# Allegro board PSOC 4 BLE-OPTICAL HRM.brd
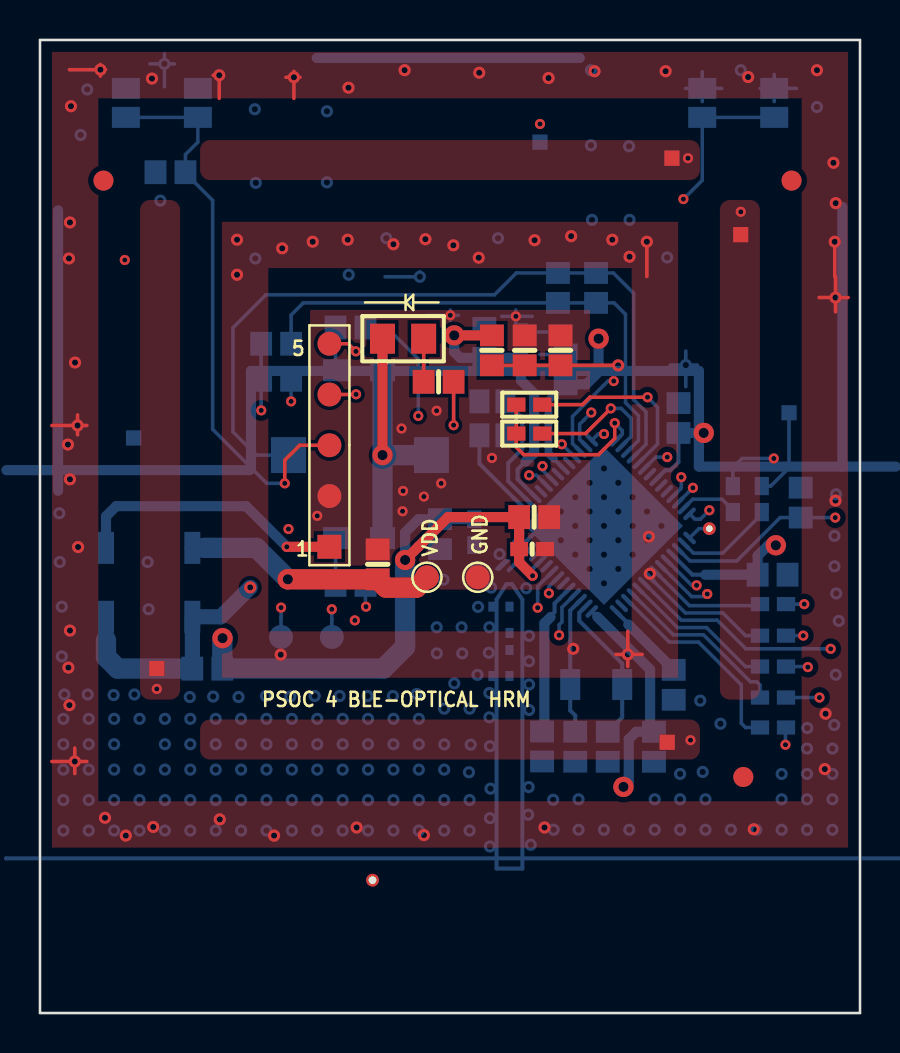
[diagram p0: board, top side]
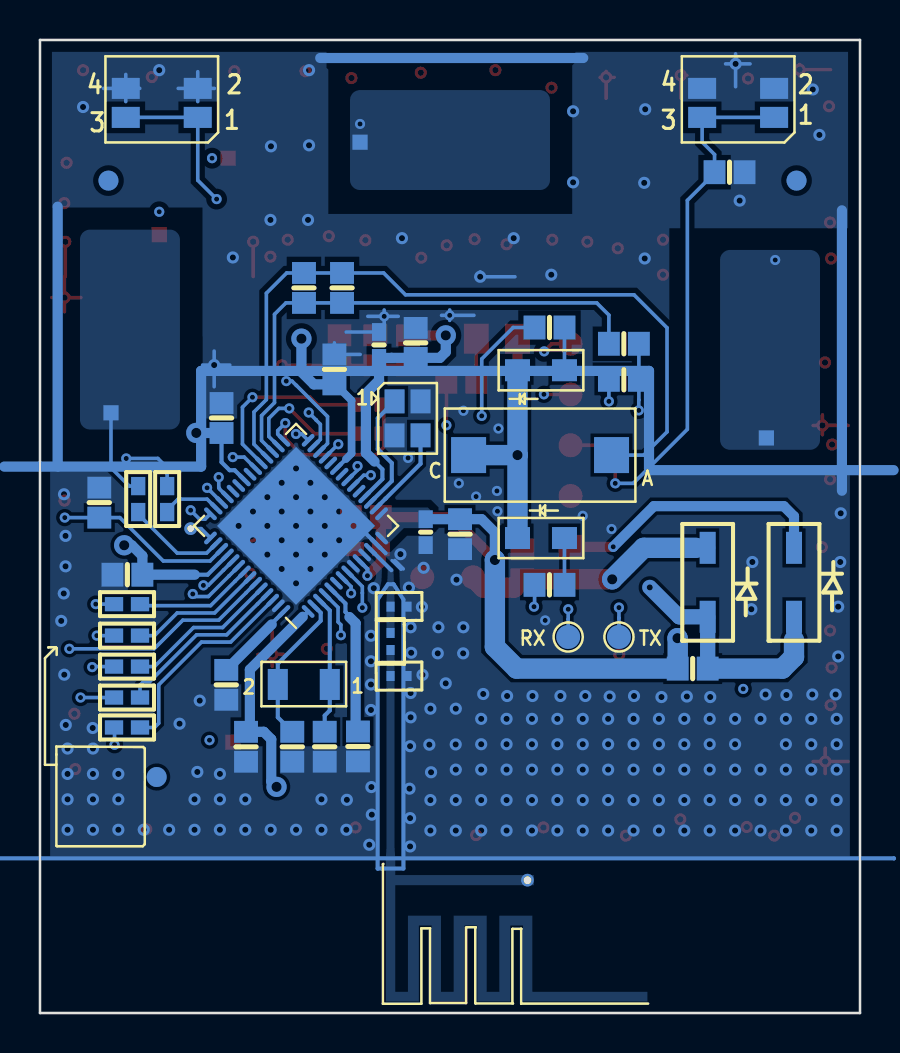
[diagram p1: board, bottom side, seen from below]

Outline 41.02 x 48.69 mm; copper layers: TOP, SHIELD, GND, BOTTOM. Coordinates in mm from the lower left corner of the outline.
Outline path: 0,48.69 0,0 41.02,0 41.02,48.69 0,48.69

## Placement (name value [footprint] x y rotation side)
ANT1  50 Ohm Wiggle Antenna  [ANTENNA15]  16.63 6.65 0 bottom
C1  12.5 pF  [C-CC0603]  26.77 13.33 270 bottom
C2  12.5 pF  [C-CC0603]  28.4 13.32 270 bottom
C3  4.7uF  [C-CC0603]  25.91 36.29 270 bottom
C4  1.2 pF  [CC0402]  23.48 18.85 270 bottom
C5  1.2 pF  [CC0402_1]  23.32 16.87 180 bottom
C6  1uF  [C-CC0603]  11.81 33.49 180 bottom
C7  47 pF  [C-CC0603]  24.24 33.16 90 top
C8  100 pF  [C-CC0603]  6.53 42.08 180 bottom
C9  0.1 uF  [C-CC0402]  24.06 33.43 90 bottom
C10  1.0 uF  [C-CC0603]  22.22 33.53 90 bottom
C11  0.1 uF  [C-CC0402]  21.73 24.06 270 bottom
C12  1.0 uF  [C-CC0603]  20.01 23.96 270 bottom
C13  2200 pF  [C-CC0603]  25.11 13.34 270 bottom
C14  0.1 uF  [C-CC0402]  24.61 23.22 0 top
C15  1.0 uF  [C-CC0603]  24.72 24.82 0 top
C16  0.1uF  [C-CC0603]  30.71 13.32 270 bottom
C18  0.1uF  [C-CC0603]  36.64 21.93 0 bottom
C19  0.1uF  [C-CC0603]  26.29 32.21 90 bottom
C20  0.1uF  [C-CC0603]  31.94 29.78 90 bottom
C26  10uF  [C-CC0603]  16.89 22.45 90 top
C27  1.0 uF  [C-CC0603]  38.05 25.54 90 bottom
C28  1.0 uF  [C-CC0603]  31.7 16.42 270 bottom
CS1  Prox - Top  [CAPSENCE]  -214.77 -180.74 0 top
CS2  Button - Top  [CAPSENCE]  271.39 -179.94 180 bottom
CS3  Prox - Left  [CAPSENCE]  -240.54 -206.28 0 top
CS4  Button - Left  [CAPSENCE]  251.06 -194.74 180 bottom
CS5  Prox - Bottom  [CAPSENCE]  -215.01 -209.97 0 top
CS6  Button - Right  [CAPSENCE]  283.85 -193.48 180 bottom
CS7  Prox - Right  [CAPSENCE]  -211.33 -184.57 0 top
D1  PHOTODIODE  [PHOTO_DIODE]  16 27.92 0 bottom
D2  MBR0520L  [SOD123]  3.3 21.55 90 bottom
D3  MBR0520L  [SOD123]  7.62 21.55 90 bottom
J1  HEADER 1  [HEAD_5_2P54_40X80_420]  14.48 28.41 90 top
L1  6.8nH  [CC0402_1]  22.8 20.33 0 bottom
LED1  LED InfraRed  [LED]  15.96 32.17 0 bottom
LED2  LED InfraRed  [LED]  15.96 23.77 0 bottom
LED3  Status LED Green  [L0805]  18.16 33.75 180 top
NOREF  -  []  41.02 0 90 top
NOREF#2  -  []  0 48.69 0 top
NOREF#3  -  [unnamed#2]  3.17 41.66 0 top
NOREF#4  -  []  162.81 -147.99 0 top
NOREF#5  -  [unnamed#2]  37.59 41.66 0 top
NOREF#6  -  [unnamed#2]  35.18 11.81 0 top
NOREF#7  -  [unnamed#2]  3.17 41.66 180 bottom
NOREF#8  -  [unnamed#2]  37.59 41.66 180 bottom
NOREF#9  -  [unnamed#2]  35.18 11.81 180 bottom
R1  330 ohm  [R-CR0603]  15.53 34.3 180 bottom
R2  330 ohm  [R-CR0603]  15.53 21.43 180 bottom
R3  10K  [R-CR0603]  27.81 36.29 90 bottom
R5  75K  [R-CR0603]  11.81 31.69 0 bottom
R6  330 ohm  [R-CR0603]  19.94 31.59 180 top
R7  1M ohm  [R-CR0603]  22.61 33.16 90 top
R8  75K  [R0402-IPC]  25.12 30.44 180 top
R9  1M ohm  [R-CR0603]  26.04 33.16 270 top
R10  560 ohm  [R0402-IPC]  36.1 26.37 270 bottom
R11  560 ohm  [R0402-IPC]  37.31 17.34 180 bottom
R12  560 ohm  [R0402-IPC]  34.66 26.37 270 bottom
R13  560 ohm  [R0402-IPC]  37.31 15.79 180 bottom
R14  560 ohm  [R0402-IPC]  37.31 20.46 180 bottom
R15  560 ohm  [R0402-IPC]  37.31 14.29 180 bottom
R16  560 ohm  [R0402-IPC]  37.31 18.89 180 bottom
R17  Zero Ohm  [R-CR0603]  8.37 17.24 180 bottom
R18  75K  [R0402-IPC]  25.12 29 180 top
SW1  SW RA PUSH  [SW_4P_3P6_52X42_54]  6.1 45.54 0 bottom
SW2  SW RA PUSH  [SW_4P_3P6_52X42_54]  34.92 45.54 0 bottom
TP1  RED  [TP_48]  12.06 18.82 180 bottom
TP2  RED  [TP_48]  14.6 18.82 180 bottom
TP3  RED  [TP_48]  19.35 21.81 0 top
TP4  RED  [TP_48]  21.89 21.81 0 top
U1  PSoC4 BLE  [QFN40P700X700X60-57T570X570N]  28.21 24.38 135 bottom
U2  HASH GND  [VIA_25X13_SHIELD]  33.48 24.24 0 top
Y1  32.768KHz  [CRY_2_2P6_40X62_32]  27.82 16.44 0 bottom
Y2  24MHz  [CRY_4_1P7_80X100_22]  22.63 29.76 270 bottom

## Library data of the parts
ANT1 = Wiggle Antenna_0
C1 C2 = CAP NP
C3 C6 C7 C9 C11 C14 = 0_0.1 uFd 0402: alternate symbols: (C-CC0603_A)
C4 C5 C13 = CAP
C8 C10 C12 C15 C26-C28 = 1_0.0 uFd 0603 X5R 25V 10%: alternate symbols: (C-CC0603_A)
C16 C18-C20 = CAPACITOR NON-POL
CS1-CS7 = CapSense Sensor_0
D1 = PHOTODIODE_1
D2 D3 = TMP_134158: User Part Number: PART_NO; Tolerance: TOLERANCE
J1 = HEADER 5
L1 = INDUCTOR
LED1 LED2 = LED Green 0805_0
LED3 = LED Green 0805_0: User Part Number: PART_NO; Tolerance: TOLERANCE
R1-R3 R5-R9 R18 = 330 ohm 5% 0805_1
R10-R16 = RESISTOR
R17 = 330 ohm 5% 0805_0
SW1 SW2 = Switch RA Pushbutton_0
TP1-TP4 = TEST_POINT: Tolerance: TOLERANCE; User Part Number: PART_NO
U1 = PSoC_BLE_6
U2 = Hash GND
Y1 = 32_0.768KHz XTAL_5P
Y2 = ZTA_14

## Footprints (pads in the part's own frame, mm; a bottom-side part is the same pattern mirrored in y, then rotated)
ANTENNA15
  round 0.635 hole 0.381: 1(0,0)
C-CC0402
  rect 0.889x0.711 smd: 1(-0.648,0) 2(0.648,0)
C-CC0603
  rect 1.092x1.194 smd: 1(-0.749,0) 2(0.749,0)
CAPSENCE
  rect 0.762x0.762 smd: 1(246.38,223.52)
CC0402
  rect 0.5x0.406 smd: 1(-0.166,0) 2(0.686,0)
CC0402_1
  rect 0.406x0.5 smd: 1(-0.166,0) 2(0.686,0)
CRY_2_2P6_40X62_32
  rect 1x1.55 smd: 1(-1.3,0) 2(1.3,0)
CRY_4_1P7_80X100_22
  rect 1.2x1 smd: 1(-0.85,-0.65) 2(0.85,-0.65) 3(0.85,0.65) 4(-0.85,0.65)
HEAD_5_2P54_40X80_420
  rect 1.2x1.2 smd: 1(-5.08,0)
  round 1.2 smd: 2(-2.54,0) 3(0,0) 4(2.54,0) 5(5.08,0)
L0805
  rect 1.25x1.5 smd: 1(-1.03,0) 2(1.03,0)
LED
  rect 1.25x1.1 smd: 1(-1.175,0) 2(1.175,0)
PHOTO_DIODE
  rect 1.75x1.8 smd: 1(-3.575,0) 2(3.575,0)
QFN40P700X700X60-57T570X570N
  oval 0.22x0.81 smd: 1(-2.6,-3.455) 2(-2.2,-3.455) 3(-1.8,-3.455) 4(-1.4,-3.455) 5(-1,-3.455) 6(-0.6,-3.455) 7(-0.2,-3.455) 8(0.2,-3.455) 9(0.6,-3.455) 10(1,-3.455) 11(1.4,-3.455) 12(1.8,-3.455) 13(2.2,-3.455) 14(2.6,-3.455) 29(2.6,3.455) 30(2.2,3.455) 31(1.8,3.455) 32(1.4,3.455) 33(1,3.455) 34(0.6,3.455) 35(0.2,3.455) 36(-0.2,3.455) 37(-0.6,3.455) 38(-1,3.455) 39(-1.4,3.455) 40(-1.8,3.455) 41(-2.2,3.455) 42(-2.6,3.455)
  oval 0.81x0.22 smd: 15(3.455,-2.6) 16(3.455,-2.2) 17(3.455,-1.8) 18(3.455,-1.4) 19(3.455,-1) 20(3.455,-0.6) 21(3.455,-0.2) 22(3.455,0.2) 23(3.455,0.6) 24(3.455,1) 25(3.455,1.4) 26(3.455,1.8) 27(3.455,2.2) 28(3.455,2.6) 43(-3.455,2.6) 44(-3.455,2.2) 45(-3.455,1.8) 46(-3.455,1.4) 47(-3.455,1) 48(-3.455,0.6) 49(-3.455,0.2) 50(-3.455,-0.2) 51(-3.455,-0.6) 52(-3.455,-1) 53(-3.455,-1.4) 54(-3.455,-1.8) 55(-3.455,-2.2) 56(-3.455,-2.6)
  rect 5.588x5.588 smd: 57(0,0)
R0402-IPC
  rect 0.914x0.711 smd: 1(0,0) 2(1.3,0)
R-CR0603
  rect 1.092x1.194 smd: 1(-0.749,0) 2(0.749,0)
SOD123
  rect 1.6x0.8 smd: 1(-1.725,0) 2(1.725,0)
SW_4P_3P6_52X42_54
  rect 1.4x1.05 smd: 1(-1.8,0.725) 2(-1.8,-0.725) 3(1.8,0.725) 4(1.8,-0.725)
TP_48
  round 1.2 smd: 1(0,0)
unnamed#2
  round 1.001 smd: (0,0)
VIA_25X13_SHIELD
  round 0.635 hole 0.33: 1(0,0)

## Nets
GND_SIGNAL: ANT1.1 C1.2 C2.2 C4.2 C5.1 C5.2 C7.2 C8.2 C9.2 C10.2 C11.2 C12.2 C13.2 C14.2 C15.2 C16.2 C18.2 C19.2 C20.2 C26.2 C27.2 C28.2 J1.2 L1.1 R9.1 SW1.2 SW1.4 SW2.2 SW2.4 TP4.1 U1.9(VSSD) U1.11(GANT1) U1.13(GANT2) U1.55(VSSA) U1.57(EPAD) Y2.2 Y2.4
VCCD: C28.1 U1.56(VCCD)
VDD: C9.1 C10.1 C11.1 C12.1 C14.1 C15.1 C16.1 C18.1 C19.1 C20.1 R7.2 R17.1 U1.1(VDDD) U1.10(VDDR#10) U1.14(VDDR#14) U1.15(VDDR#15) U1.18(VDDR_1) U1.23(VDDD_1) U1.36(VDDA#36) U1.46(VDDA#46)
VDD_IN: D1.2(CATHODE) D2.1(CATHODE) D3.1(CATHODE) LED1.2(A) LED2.2(A) LED3.2(A) R17.2
/XRES: C8.1 J1.3 SW1.1 SW1.3 U1.4(XRES)
BLE_STATUS: R6.1 U1.25(P0.5)
BUF_IN: C7.1 R7.1 R9.2 U1.34(P1.6) U1.42(P2.5)
BUF_OUT: R5.2 R8.1 U1.33(P1.5) U1.40(P2.3) U1.48(P3.1)
CMOD: C13.1 U1.5(P4.0)
CS_LEFT: R16.2 U1.50(P3.3)
CS_RIGHT: R10.2 U1.44(P2.7)
CS_TOP: R14.2 U1.49(P3.2)
LED_IR_1: R2.1 U1.21(P0.2)
LED_IR_2: R1.1 U1.20(P0.1)
P1.0: C6.2 R5.1 U1.28(P1.0)
P1.1: R8.2 R18.2 U1.29(P1.1)
P1.2: R18.1 U1.30(P1.2) U1.47(P3.0)
P1.3: C3.2 C6.1 R3.1 U1.31(P1.3)
P1.4: C3.1 D1.1(ANODE) R3.2 U1.32(P1.4)
PS_BOTTOM: R15.2 U1.54(P3.7)
PS_LEFT: R11.2 U1.52(P3.5)
PS_RIGHT: R13.2 U1.53(P3.6)
PS_TOP: R12.2 U1.41(P2.4)
RX: TP2.1 U1.7(P5.0)
SHIELD: U1.43(P2.6) U2.1(SHIELD/GND)
SWD_CLK: J1.4 U1.27(P0.7)
SWD_DATA: J1.5 U1.26(P0.6)
TX: TP1.1 U1.8(P5.1)
VREF: C27.1 U1.45(VREF) U1.51(P3.4)
WAKEUP: SW2.1 SW2.3 U1.39(P2.2)
XTAL24I: U1.16(XTAL24I) Y2.3
XTAL24O: U1.17(XTAL24O) Y2.1
XTAL32I: C1.1 U1.3(XTAL32I/P6.1) Y1.1
XTAL32O: C2.1 U1.2(XTAL32O/P6.0) Y1.2
N05559: LED3.1(K) R6.2
N16776133: CS7.1 R13.1
N16776137: CS1.1 R12.1
N16776145: CS5.1 R15.1
N16776149: CS3.1 R11.1
N16783830: LED2.1(K) R2.2
N16783862: LED1.1(K) R1.2
N16783984: C26.1 D3.2(ANODE) TP3.1
N16844141: CS2.1 R14.1
N16844145: CS4.1 R16.1
N16865210: C4.1 L1.2 U1.12(ANT)
N16879821: CS6.1 R10.1
N167810750: D2.2(ANODE) J1.1

Pads without a net: U1 6 19 22 24 35 37 38

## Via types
v1: diameter 0.508, hole 0.254, TOP to BOTTOM, 57 vias
v2: diameter 0.61, hole 0.305, GND to BOTTOM, 215 vias
v3: diameter 0.61, hole 0.305, TOP to SHIELD, 60 vias
v4: diameter 1.016, hole 0.508, TOP to BOTTOM, 9 vias
v5: diameter 0.61, hole 0.305, TOP to BOTTOM, 1 via

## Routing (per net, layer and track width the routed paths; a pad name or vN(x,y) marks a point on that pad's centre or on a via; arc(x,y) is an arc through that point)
GND_SIGNAL: length 134.1
  GND w0.178: 32.3,32.26 v2(32.3,32.43) ; v2(32.3,32.43) 32.49,32.43 ; v2(32.3,32.43) 32.14,32.43 ; 33.98,47.18 v2(35.05,47.18) ; v2(35.05,47.18) 35.05,46.11 ; v2(35.05,47.18) 35.05,48.1 ; v2(35.05,47.18) 36.18,47.18 ; 10.74,43.87 v2(10.74,45.23) ; v2(10.74,45.23) 9.33,45.23 ; v2(10.74,45.23) 11.04,45.23 ; v2(10.74,45.23) 10.74,45.46 ; v2(2.03,43.94) 2.52,43.94 ; v2(2.03,43.94) 2.03,45.94 ; v2(2.03,43.94) 1.26,43.94 ; v2(2.03,43.94) 2.03,43.46 ; 27.56,42.54 v2(27.56,43.42) ; v2(27.56,43.42) 29.44,43.42 ; v2(27.56,43.42) 27.56,44.09 ; v2(27.56,43.42) 26.89,43.42 ; v1(20.52,34.91) 20.52,35.75 ; v1(20.52,34.91) 18.59,34.91 ; v1(20.52,34.91) 20.52,34.69 ; v1(20.52,34.91) 21.15,34.91 ; 14.88,36.95 v2(15.44,36.95) ; v2(15.44,36.95) 15.44,37.51 ; v2(15.44,36.95) 16.56,36.95 ; v2(15.44,36.95) 15.44,35.29 ; v2(14.35,45.12) 14.35,45.46 ; v2(14.35,45.12) 14.35,44.71 ; v2(14.35,45.12) 13.91,45.12 ; v2(14.35,45.12) 14.76,45.12 ; 38.86,45.07 v2(38.86,45.34) ; v2(38.86,45.34) 38.59,45.34 ; v2(38.86,45.34) 39.87,45.34 ; v2(38.86,45.34) 38.86,47.1 ; 10.77,37.2 v2(10.77,37.76) ; v2(10.77,37.76) 10.21,37.76 ; v2(10.77,37.76) 12.93,37.76 ; v2(10.77,37.76) 10.77,38.36 ; 6.07,47.5 v2(6.22,47.5) ; v2(6.22,47.5) 6.22,47.65 ; v2(6.22,47.5) 6.22,47.28 ; 14.35,39.19 v2(14.35,41.57) ; v2(14.35,41.57) 14.35,41.92 ; v2(14.35,41.57) 13.97,41.57 ; v2(14.35,41.57) 14.7,41.57 ; 25.68,47.18 v2(27.56,47.18) ; v2(27.56,47.18) 27.56,48.07 ; v2(27.56,47.18) 27.56,46.86 ; v2(27.56,47.18) 27.89,47.18 ; v2(19,36.84) 19.43,36.84 ; v2(19,36.84) 19,35.53 ; v2(19,36.84) 17.55,36.84 ; v2(19,36.84) 19,37.27 ; 10.79,41.16 v2(10.79,41.54) ; v2(10.79,41.54) 10.79,42.71 ; v2(10.79,41.54) 11.18,41.54 ; v2(10.79,41.54) 9.19,41.54 ; v2(6.02,40.65) 7.32,40.65 ; v2(6.02,40.65) 6.02,39.19 ; v2(6.02,40.65) 6.02,41.91 ; v2(6.02,40.65) 4.76,40.65 ; 31.37,36.84 v2(31.37,37.81) ; v2(31.37,37.81) 29.58,37.81 ; v2(31.37,37.81) 32.29,37.81 ; v2(31.37,37.81) 31.37,38.73 ; v2(29.49,39.69) 29.49,40.49 ; v2(29.49,39.69) 28.69,39.69 ; v2(29.49,39.69) 29.49,37.84 ; v2(29.49,39.69) 30.41,39.69 ; 17.32,36.62 v2(17.32,38.77) ; v2(17.32,38.77) 17.5,38.77 ; v2(17.32,38.77) 17.32,38.95 ; v2(17.32,38.77) 16.71,38.77 ; 2.03,46.22 v2(2.36,46.22) ; v2(2.36,46.22) 2.36,45.61 ; v2(2.36,46.22) 2.36,46.55 ; v2(2.36,46.22) 4.52,46.22
  BOTTOM w0.152: 23.41,22.65 22.96,22.2
  BOTTOM w0.178: 36.72,45.61 SW2.4 ; SW2.4 36.72,46.97 ; SW2.4 37.84,46.27 ; SW2.4 36.03,46.27 ; 31.52,32.43 v2(32.3,32.43) ; v2(32.3,32.43) 32.3,31.34 ; v2(32.3,32.43) 32.3,33.13 ; v2(32.3,32.43) 32.88,32.43 ; C9.2 24.06,34.3 ; C9.2 25.7,34.08 ; C9.2 24.06,33.9 ; C9.2 23.88,34.08 ; v2(6.22,47.5) 6.22,48 ; v2(6.22,47.5) 6.72,47.5 ; v2(6.22,47.5) 5.5,47.5 ; v2(6.22,47.5) 6.22,46.35 ; v1(20.52,34.91) 20.93,34.91 ; v1(20.52,34.91) 19.31,34.91 ; v1(20.52,34.91) 20.52,34.66 ; v1(20.52,34.91) 20.52,35.18 ; C19.2 26.45,32.96 ; C19.2 26.29,32.8 ; C19.2 26.29,33.54 ; C19.2 25,32.96 ; 23.8,34.16 v1(23.8,34.86) ; v1(23.8,34.86) 23.1,34.86 ; v1(23.8,34.86) 24.62,34.86 ; v1(23.8,34.86) 23.8,35.18 ; v2(19,36.84) 19.13,36.84 ; v2(19,36.84) 19,36.72 ; v2(19,36.84) 17.26,36.84 ; v2(19,36.84) 19,37.09 ; SW2.2 33.13,47.11 ; SW2.2 32.29,46.27 ; SW2.2 33.13,45.61 ; SW2.2 34.1,46.27 ; 23.27,22.65 22.85,22.22
  BOTTOM w0.203: 24.69,23.97 U1.13 23.73,23.01
  BOTTOM w0.508: 13.84,47.79 27,47.79 ; 40.13,27.34 40.13,40.35 ; 0.9,26.14 0.9,40.17
  vias: v1(12.43,24.22) v1(13.87,24.88) v1(15.75,19.65) v1(18.08,29.25) v1(18.14,25.11) v1(18.16,26.13) v1(19.2,25.85) v1(19.84,30.14) v1(20.07,26.51) v1(22.61,27.78) v2(0.97,25.01) v2(0.99,22.57) v2(1.09,20.33) v2(1.09,17.85) v2(1.22,15.94) v2(1.17,14.72) v2(1.17,13.45) v2(1.17,12.18) v2(1.17,10.66) v2(1.17,9.13) v2(2.39,15.94) v2(2.44,14.72) v2(2.44,13.45) v2(2.44,12.18) v2(2.44,10.66) v2(2.44,9.13) v2(3.68,15.91) v2(3.71,14.72) v2(3.71,13.45) v2(3.71,12.18) v2(3.71,10.66) v2(3.71,9.13) v2(4.72,15.94) v2(4.98,14.72) v2(4.98,12.18) v2(4.98,10.66) v2(4.98,9.13) v2(5.38,22.57) v2(5.44,20.21) v2(6.25,14.72) v2(6.25,13.45) v2(6.25,12.18) v2(6.25,10.66) v2(6.25,9.13) v2(7.49,15.81) v2(7.52,14.72) v2(7.52,13.45) v2(7.52,12.18) v2(7.52,10.66) v2(7.52,9.13) v2(8.66,15.84) v2(8.79,14.72) v2(8.79,13.45) v2(8.79,12.18) v2(8.79,10.66) v2(8.79,9.13) v2(9.93,15.81) v2(10.06,14.72) v2(10.06,13.45) v2(10.06,12.18) v2(10.06,10.66) v2(10.06,9.13) v2(11.3,15.86) v2(11.33,14.72) v2(11.33,13.45) v2(11.33,12.18) v2(11.33,10.66) v2(11.33,9.13) v2(12.52,15.84) v2(12.6,14.72) v2(12.6,13.45) v2(12.6,12.18) v2(12.6,10.66) v2(12.6,9.13) v2(13.74,15.86) v2(13.87,14.72) v2(13.87,13.45) v2(13.87,12.18) v2(13.87,10.66) v2(13.87,9.13) v2(14.99,15.86) v2(15.14,14.72) v2(15.14,13.45) v2(15.14,12.18) v2(15.14,10.66) v2(15.14,9.13) v2(16.38,15.86) v2(16.41,14.72) v2(16.41,13.45) v2(16.41,12.18) v2(16.41,10.66) v2(16.41,9.13) v2(17.65,15.86) v2(17.68,14.72) v2(17.68,13.45) v2(17.68,12.18) v2(17.68,10.66) v2(17.68,9.13) v2(18.85,15.97) v2(18.95,14.72) v2(18.95,13.45) v2(18.95,12.18) v2(18.95,10.66) v2(18.95,9.13) v2(19.84,19.3) v2(19.85,18) v2(20.18,21.68) v2(20.22,15.23) v2(20.22,13.44) v2(20.22,12.18) v2(20.22,10.66) v2(20.22,9.13) v2(20.72,16.5) v2(21.09,19.31) v2(21.12,18) v2(21.49,15.23) v2(21.54,13.43) v2(21.46,12.05) v2(21.49,10.66) v2(21.49,9.13) v2(21.83,22.28) v2(21.91,20.32) v2(21.88,16.92) v2(22.48,19.3) v2(22.45,18.03) v2(22.48,16.02) v2(22.48,14.8) v2(22.5,13.35) v2(22.53,11.23) v2(22.5,9.75) v2(22.5,8.34) v2(22.56,21.29) v2(22.91,38.77) v2(22.99,22.96) v2(24.32,21.26) v2(24.44,11.31) v2(24.42,9.93) v2(24.46,18.88) v2(24.46,17.6) v2(24.46,16.44) v2(24.46,15.17) v2(24.55,8.42) v2(25.33,24.38) v2(25.67,10.67) v2(25.69,9.17) v2(26.05,25.1) v2(26.05,23.66) v2(26.77,25.81) v2(26.77,24.38) v2(26.77,22.94) v2(26.94,10.7) v2(26.94,9.17) v2(27.49,26.53) v2(27.49,25.1) v2(27.49,23.66) v2(27.49,22.22) v2(27.61,39.69) v2(28.21,27.25) v2(28.21,25.81) v2(28.21,24.38) v2(28.21,22.94) v2(28.21,21.5) v2(28.21,9.17) v2(28.93,26.53) v2(28.93,25.1) v2(28.93,23.66) v2(28.93,22.22) v2(29.46,43.37) v2(29.48,9.17) v2(29.64,25.81) v2(29.64,24.38) v2(29.64,22.94) v2(30.36,25.1) v2(30.36,23.66) v2(30.75,10.7) v2(30.75,9.17) v2(31.08,24.38) v2(32.02,11.97) v2(32.02,10.7) v2(32.02,9.17) v2(33.03,15.63) v2(33.15,12.06) v2(33.29,10.7) v2(33.29,9.17) v2(34.04,14.48) v2(34.56,9.17) v2(35.83,9.17) v2(37.1,11.97) v2(37.1,10.7) v2(37.1,9.17) v2(38.38,14.26) v2(38.37,13.24) v2(38.37,11.97) v2(38.37,10.7) v2(38.37,9.17) v2(39.64,13.24) v2(39.64,11.97) v2(39.64,10.7) v2(39.64,9.17) v2(39.74,23.88) v2(39.74,22.35) v2(39.73,14.42) v2(39.81,25.96) v2(39.83,20.99) v2(39.8,16.93) v2(39.95,19.62)
VCCD: length 4.1
  BOTTOM w0.178: 29.43,19.48 29.43,19.45
  BOTTOM w0.203: U1.56 29.43,19.48
  BOTTOM w0.508: 29.43,19.45 C28.1
VDD: length 158.9
  TOP w0.508: v1(24.64,21.88) 23.97,22.55 C14.1 C15.1 20.41,24.82 18.93,23.34 v4(18.26,22.67) ; R7.2 v4(20.72,33.91)
  SHIELD w1.016: v4(9.13,18.76) 9.13,34 11.73,36.59 25.09,36.59 27.1,34.59 v4(27.94,33.75) 27.95,33.73 29.69,33.73 33.2,30.22 v4(33.2,29.03) 36.8,25.42 v4(36.8,23.41) 36.8,21.81 29.18,14.19 v4(29.18,11.32)
  GND w1.016: v4(20.72,33.91) 19.36,33.91 16.95,31.49 16.95,30.42 15.64,29.11 15.64,23.59 16.56,22.67 v4(18.26,22.67)
  BOTTOM w0.178: 27.87,19.83 27.87,19.83
  BOTTOM w0.203: 25.71,27.72 U1.23 ; 33.27,21.93 32.63,21.93 U1.46 ; U1.10 24.64,22.22 v1(24.64,21.88) ; U1.18 23.89,26.72 23.89,27.21 24.28,27.6 ; U1.36 31.28,27.16 31.53,27.16 31.94,27.57 C20.1 ; U1.1 27.87,19.83
  BOTTOM w0.381: C19.1 26.24,31.46 25.43,30.65 25.43,28 25.71,27.72
  BOTTOM w0.508: v4(20.72,33.91) 20.72,33.08 21.02,32.79 C10.1 23.43,32.79 23.43,32.78 C9.1 24.06,31.66 24.71,31 24.71,28.03 24.28,27.6 ; 27.87,19.83 30.52,17.18 30.52,14.26 C16.1 29.82,14.07 29.45,13.7 29.45,11.58 v4(29.18,11.32) ; v4(27.94,33.75) 27.94,32.08 27.32,31.46 C19.1 ; v4(33.2,29.03) 33.19,29.03 C20.1 ; v4(18.26,22.67) 18.26,24.05 18.93,24.71 C12.1 C11.1 ; 9.12,18.75 v4(9.13,18.76) ; v4(36.8,23.41) 36.42,23.41 35.89,22.88 C18.1 33.27,21.93
  BOTTOM w1.016: v4(18.26,22.67) 18.26,18.32 17.18,17.24 R17.1 9.12,18.75
VDD_IN: length 41.9
  TOP w0.508: v4(17.13,27.92) 17.13,32.56 17.13,32.56 LED3.2
  SHIELD w0.508: v4(17.13,27.92) 11.6,27.92 10.52,26.84 v5(10.52,21.3)
  BOTTOM w0.762: R17.2 D3.1 9.04,19.83 v5(10.52,21.3) ; D2.1 3.3,18.66
  BOTTOM w1.016: LED2.2 v4(17.13,27.92) ; v4(17.13,27.92) D1.2 ; v4(17.13,27.92) LED1.2 ; R17.2 3.89,17.24 3.3,17.82 3.3,18.66
/XRES: length 54.5
  TOP w0.178: v1(12.24,26.51) 12.24,27.66 12.99,28.41 J1.3
  SHIELD w0.178: v1(12.24,26.51) 11.3,25.57 11.3,19.9 14.19,17.02 24.08,17.02 v1(25.97,18.91)
  BOTTOM w0.178: v1(12.24,26.51) 11.34,26.51 8.64,29.21 8.64,40.67 7.28,42.03 C8.1 7.28,42.96 7.9,43.58 SW1.3 SW1.1 ; v1(25.97,18.91) 25.97,19.43 26.11,19.57 26.11,20.3 U1.4
BLE_STATUS: length 8.9
  TOP w0.178: R6.1 v1(20.69,29.41)
  SHIELD w0.178: v1(26.1,28.46) 21.64,28.46 v1(20.69,29.41)
  BOTTOM w0.178: U1.25 26.1,28.46 v1(26.1,28.46)
BUF_IN: length 19.4
  TOP w0.178: R7.1 C7.1 R9.2 28.13,32.41 28.14,32.41 v3(28.92,32.41)
  SHIELD w0.178: v3(28.92,32.41) 29.67,32.41 31.37,30.71 v1(31.37,27.82) 32.83,27.82 33.48,27.17 v1(33.48,25.16)
  BOTTOM w0.178: v1(31.37,27.82) 30.8,27.82 30.23,27.25 U1.34 ; U1.42 32.76,24.72 33.04,24.72 v1(33.48,25.16)
BUF_OUT: length 45.7
  TOP w0.178: R8.1 27.13,30.44 27.5,30.82 v1(30.39,30.82)
  SHIELD w0.178: v1(12.56,30.61) 13.58,31.63 14.46,32.51 26.95,32.51 28.64,30.82 v1(30.39,30.82) 30.39,26.96 31.06,26.28 v1(32.66,26.28) 32.66,23.55 33.38,22.83 v1(33.38,20.97)
  BOTTOM w0.178: v1(32.66,26.28) 32.49,26.11 U1.40 ; U1.33 30.89,28.47 30.89,30.31 v1(30.39,30.82) ; v1(33.38,20.97) 33.25,20.84 32.59,20.84 31.55,21.88 U1.48 ; R5.2 v1(12.56,30.61)
CMOD: length 7.7
  BOTTOM w0.203: U1.5 25.99,20.74 25.74,20.49 25.74,20.07 25.54,19.87 25.54,19.82
  BOTTOM w0.508: C13.1 25.23,14.2 25.23,19.51 25.54,19.82
CS_LEFT: length 6.7
  BOTTOM w0.178: U1.50 32.28,20.02 34.16,20.02 35.29,18.89 R16.2
CS_RIGHT: length 5
  BOTTOM w0.178: U1.44 32.68,23.02 34.15,23.02 36.1,24.97 R10.2
CS_TOP: length 6
  BOTTOM w0.178: U1.49 31.27,21.6 32.48,20.39 35.94,20.39 R14.2
LED_IR_1: length 15.7
  SHIELD w0.178: v1(16.31,20.33) 21.39,20.33 25.13,24.08 v1(25.13,27.37)
  BOTTOM w0.178: U1.21 25.13,27.17 v1(25.13,27.37) ; R2.1 16.28,21.43 16.28,20.36 v1(16.31,20.33)
LED_IR_2: length 14
  SHIELD w0.178: v1(18.92,29.88) 21.89,26.91 v1(24.47,26.91)
  BOTTOM w0.178: U1.20 24.83,26.91 v1(24.47,26.91) ; R1.1 17.35,34.3 18.92,32.73 v1(18.92,29.88)
P1.0: length 22.6
  SHIELD w0.178: v1(11.07,30.16) 11.62,29.6 15.85,29.6 16.94,30.7 25.23,30.7 26.95,28.98 v1(28.21,28.98)
  BOTTOM w0.178: U1.28 27.92,28.98 v1(28.21,28.98) ; v1(11.07,30.16) 11.07,30.68 11.06,30.68 R5.1 C6.2
P1.1: length 9.5
  TOP w0.178: R8.2 R18.2 23.82,28.32 24.2,27.94 27.93,27.94 28.75,28.75 v1(28.75,29.52)
  BOTTOM w0.178: U1.29 29.13,28.97 29.13,29.14 v1(28.75,29.52)
P1.2: length 19.9
  TOP w0.178: v1(28.55,30.26) 27.29,29 R18.1
  SHIELD w0.178: v1(28.55,30.26) 29.48,30.26 29.88,29.86 29.88,25.82 32.84,22.85 v1(32.84,21.4)
  BOTTOM w0.178: v1(32.84,21.4) 32.6,21.4 31.83,22.17 U1.47 ; v1(28.55,30.26) 29.07,30.26 29.57,29.76 29.57,28.85 U1.30
P1.3: length 26
  BOTTOM w0.178: C6.1 12.56,34.93 13.17,35.54 C3.2 R3.1 28.71,35.54 29.29,34.96 29.29,30.54 29.93,29.9 29.93,28.65 U1.31
P1.4: length 38.8
  BOTTOM w0.178: U1.32 30.31,28.46 30.31,30.08 29.69,30.7 29.69,36.02 28.68,37.03 R3.2 C3.1 23.83,37.03 22.73,35.94 11.3,35.94 9.65,34.29 9.65,29.08 10.81,27.92 D1.1
PS_BOTTOM: length 10.4
  BOTTOM w0.178: R15.2 35.29,14.29 35.08,14.5 35.08,16.42 32.94,18.56 31.48,18.56 U1.54
PS_LEFT: length 7.7
  BOTTOM w0.178: U1.52 31.88,19.29 33.34,19.29 35.29,17.34 R11.2
PS_RIGHT: length 8.9
  BOTTOM w0.178: R13.2 36.01,16.41 35.85,16.58 35.53,16.58 33.18,18.93 31.68,18.93 30.14,20.47 U1.53
PS_TOP: length 3
  BOTTOM w0.178: U1.41 32.66,25.72 34.11,25.72 34.66,25.17 R12.2
RX: length 15
  SHIELD w0.178: v1(14.6,20.21) 14.6,19.68 15.39,18.89 21.29,18.89 23.41,21 v1(25.46,21)
  BOTTOM w0.178: TP2.1 14.6,19.71 14.6,19.71 v1(14.6,20.21) ; v1(25.46,21) 25.46,21.34 U1.7
SHIELD: length 172.2
  TOP w0.178: v3(30.35,38.6) 30.35,38.73 ; v3(30.35,38.6) 30.35,36.86 ; v3(30.35,38.6) 30.22,38.6 ; v3(30.35,38.6) 30.57,38.6 ; 39.56,38.6 v3(39.75,38.6) ; v3(39.75,38.6) 39.91,38.6 ; v3(39.75,38.6) 39.75,38.75 ; v3(39.75,38.6) 39.75,36.86 ; 1.47,47.21 v3(3.02,47.21) ; v3(3.02,47.21) 3.02,46.89 ; v3(3.02,47.21) 3.28,47.21 ; v3(3.02,47.21) 3.02,47.46 ; v3(29.4,17.95) 29.4,19.1 ; v3(29.4,17.95) 29.4,17.35 ; v3(29.4,17.95) 28.8,17.95 ; v3(29.4,17.95) 30.12,17.95 ; v3(1.88,29.4) 1.88,29.93 ; v3(1.88,29.4) 2.35,29.4 ; v3(1.88,29.4) 0.6,29.4 ; v3(1.88,29.4) 1.88,28.94 ; v3(1.74,12.59) 2.34,12.59 ; v3(1.74,12.59) 1.74,11.98 ; v3(1.74,12.59) 1.74,13.26 ; v3(1.74,12.59) 0.6,12.59 ; 12.7,45.77 v3(12.7,46.83) ; v3(12.7,46.83) 12.3,46.83 ; v3(12.7,46.83) 13,46.83 ; v3(12.7,46.83) 12.7,47.13 ; 8.66,46.93 v3(8.97,46.93) ; v3(8.97,46.93) 9.16,46.93 ; v3(8.97,46.93) 8.97,45.77 ; v3(8.97,46.93) 8.97,47.12 ; v3(39.79,35.8) 39.79,36.85 ; v3(39.79,35.8) 40.42,35.8 ; v3(39.79,35.8) 39.79,35.09 ; v3(39.79,35.8) 38.97,35.8
  SHIELD w0.178: v3(12.04,17.93) 12.04,18.66 ; v3(12.04,17.93) 12.04,17.51 ; v3(12.04,17.93) 10.68,17.93 ; v3(12.04,17.93) 12.47,17.93 ; 1.91,21.2 v3(1.91,23.32) ; v3(1.91,23.32) 1.91,23.94 ; v3(1.91,23.32) 1.26,23.32 ; v3(1.91,23.32) 2.53,23.32 ; 38.76,14.98 v3(39.29,14.98) ; v3(39.29,14.98) 39.93,14.98 ; v3(39.29,14.98) 39.29,14.34 ; v3(39.29,14.98) 39.29,15.37 ; v3(12.12,38.27) 12.12,38.62 ; v3(12.12,38.27) 12.47,38.27 ; v3(12.12,38.27) 12.12,37.37 ; v3(12.12,38.27) 10.67,38.27 ; 18.24,46.33 v3(18.24,47.18) ; v3(18.24,47.18) 19.59,47.18 ; v3(18.24,47.18) 17.39,47.18 ; v3(18.24,47.18) 18.24,48.1 ; v3(1.5,19.14) 1.5,20.8 ; v3(1.5,19.14) 2.61,19.14 ; v3(1.5,19.14) 1.5,18.81 ; v3(1.5,19.14) 1.17,19.14 ; 39.79,25.31 v3(39.79,25.64) ; v3(39.79,25.64) 39.54,25.64 ; v3(39.79,25.64) 39.79,25.9 ; v3(39.79,25.64) 40.42,25.64 ; v3(1.45,37.76) 1.45,38.23 ; v3(1.45,37.76) 1.45,37.34 ; v3(1.45,37.76) 1.87,37.76 ; v3(1.45,37.76) 0.6,37.76 ; v3(25.23,9.29) 25.95,9.29 ; v3(25.23,9.29) 25.23,9.97 ; v3(25.23,9.29) 25.23,8.91 ; v3(25.23,9.29) 24.86,9.29 ; v3(1.4,28.45) 2.93,28.45 ; v3(1.4,28.45) 1.4,28.99 ; v3(1.4,28.45) 1.4,27.21 ; v3(1.4,28.45) 0.85,28.45 ; 2.25,9.77 v3(3.25,9.77) ; v3(3.25,9.77) 3.25,8.76 ; v3(3.25,9.77) 4.3,9.77 ; v3(3.25,9.77) 3.25,11.48 ; 1.5,38.18 v3(1.5,39.56) ; v3(1.5,39.56) 1.5,40.16 ; v3(1.5,39.56) 2.88,39.56 ; v3(1.5,39.56) 0.9,39.56 ; 19.28,38.58 v3(19.28,38.72) ; v3(19.28,38.72) 17.55,38.72 ; v3(19.28,38.72) 19.43,38.72 ; v3(19.28,38.72) 19.28,39.76 ; v3(26.57,38.88) 27.88,38.88 ; v3(26.57,38.88) 26.57,38 ; v3(26.57,38.88) 25.69,38.88 ; v3(26.57,38.88) 26.57,40.33 ; v3(8.99,9.69) 8.99,11.32 ; v3(8.99,9.69) 8.99,8.93 ; v3(8.99,9.69) 9.76,9.69 ; v3(8.99,9.69) 7.86,9.69 ; 15.84,7.83 v3(15.84,9.29) ; v3(15.84,9.29) 15.84,9.97 ; v3(15.84,9.29) 16.56,9.29 ; v3(15.84,9.29) 14.88,9.29 ; 20.28,47.06 v3(21.97,47.06) ; v3(21.97,47.06) 21.97,48.1 ; v3(21.97,47.06) 22.23,47.06 ; v3(21.97,47.06) 21.97,46.8 ; 0.76,17.29 v3(1.42,17.29) ; v3(1.42,17.29) 3.03,17.29 ; v3(1.42,17.29) 1.42,17.95 ; v3(1.42,17.29) 1.42,16.12 ; 1.47,15.24 v3(1.47,15.41) ; v3(1.47,15.41) 1.47,16.07 ; v3(1.47,15.41) 0.6,15.41 ; v3(1.47,15.41) 1.64,15.41 ; 30.45,23.05 v3(30.45,23.84) ; v3(30.45,23.84) 29.66,23.84 ; v3(30.45,23.84) 30.45,24.74 ; v3(30.45,23.84) 31.35,23.84 ; 35.7,7.98 v3(35.7,9.2) ; v3(35.7,9.2) 34.15,9.2 ; v3(35.7,9.2) 35.7,9.51 ; v3(35.7,9.2) 36.01,9.2 ; 14.81,38.7 v3(15.39,38.7) ; v3(15.39,38.7) 16.64,38.7 ; v3(15.39,38.7) 15.39,38.11 ; v3(15.39,38.7) 15.39,40.22 ; v3(9.86,36.95) 9.86,37.45 ; v3(9.86,36.95) 9.35,36.95 ; v3(9.86,36.95) 9.86,35.81 ; v3(9.86,36.95) 10.99,36.95 ; 29.07,17.95 v3(29.4,17.95) ; v3(29.4,17.95) 29.4,18.27 ; v3(29.4,17.95) 30.03,17.95 ; v3(29.4,17.95) 29.4,15.81 ; 30.35,21.99 v3(30.51,21.99) ; v3(30.51,21.99) 31.52,21.99 ; v3(30.51,21.99) 30.51,20.23 ; v3(30.51,21.99) 30.51,22.14 ; 21.95,37.37 v3(21.95,37.8) ; v3(21.95,37.8) 24,37.8 ; v3(21.95,37.8) 21.95,38.48 ; v3(21.95,37.8) 21.27,37.8 ; v3(1.55,45.38) 2.59,45.38 ; v3(1.55,45.38) 1.55,45.74 ; v3(1.55,45.38) 1.55,43.66 ; v3(1.55,45.38) 1.19,45.38 ; v3(1.75,32.55) 2.19,32.55 ; v3(1.75,32.55) 1.75,32.39 ; v3(1.75,32.55) 1.75,34.93 ; v3(1.75,32.55) 1.59,32.55 ; 34.09,24.24 U2.1 33.48,23.63 ; v3(1.5,26.71) 1.5,27.11 ; v3(1.5,26.71) 0.6,26.71 ; v3(1.5,26.71) 1.88,26.71 ; v3(1.5,26.71) 1.5,26.33 ; 5.66,9.12 v3(5.66,9.31) ; v3(5.66,9.31) 6.61,9.31 ; v3(5.66,9.31) 5.66,11.13 ; v3(5.66,9.31) 5.47,9.31 ; 13.64,38.47 v3(13.64,38.6) ; v3(13.64,38.6) 12.14,38.6 ; v3(13.64,38.6) 13.64,39.86 ; v3(13.64,38.6) 13.77,38.6 ; 8.27,46.93 v3(8.97,46.93) ; v3(8.97,46.93) 9.34,46.93 ; v3(8.97,46.93) 8.97,44.86 ; v3(8.97,46.93) 8.97,47.3 ; v3(39.69,42.55) 39.85,42.55 ; v3(39.69,42.55) 38.62,42.55 ; v3(39.69,42.55) 39.69,44.24 ; v3(39.69,42.55) 39.69,42.39 ; 12.21,46.83 v3(12.7,46.83) ; v3(12.7,46.83) 12.7,46.34 ; v3(12.7,46.83) 13.7,46.83 ; v3(12.7,46.83) 12.7,48.1 ; 39.8,39.74 v3(39.8,40.53) ; v3(39.8,40.53) 40.42,40.53 ; v3(39.8,40.53) 37.87,40.53 ; v3(39.8,40.53) 39.8,41.36 ; v3(39.26,12.21) 39.93,12.21 ; v3(39.26,12.21) 38.53,12.21 ; v3(39.26,12.21) 39.26,14.25 ; v3(39.26,12.21) 39.26,11.53 ; v3(25.44,46.79) 26.08,46.79 ; v3(25.44,46.79) 25.44,47.43 ; v3(25.44,46.79) 24.73,46.79 ; 17.27,8.9 v3(19.2,8.9) ; v3(19.2,8.9) 19.71,8.9 ; v3(19.2,8.9) 19.2,8.07 ; v3(19.2,8.9) 19.2,9.41 ; v3(5.6,46.76) 5.6,47.03 ; v3(5.6,46.76) 5.6,45.14 ; v3(5.6,46.76) 6.74,46.76 ; v3(5.6,46.76) 5.34,46.76 ; v3(9.86,38.7) 11.1,38.7 ; v3(9.86,38.7) 9.86,40.22 ; v3(9.86,38.7) 9.27,38.7 ; v3(9.86,38.7) 9.86,38.12 ; v3(4.29,8.88) 4.29,9.76 ; v3(4.29,8.88) 5.9,8.88 ; v3(4.29,8.88) 4.29,7.83 ; v3(4.29,8.88) 3.41,8.88 ; v3(1.74,12.59) 2.19,12.59 ; v3(1.74,12.59) 1.74,10.21 ; v3(1.74,12.59) 1.59,12.59 ; v3(1.74,12.59) 1.74,12.74 ; 35.42,46.42 v3(35.42,46.84) ; v3(35.42,46.84) 35.84,46.84 ; v3(35.42,46.84) 35.42,48.1 ; v3(35.42,46.84) 34.32,46.84 ; v3(24.74,38.67) 24.91,38.67 ; v3(24.74,38.67) 23.13,38.67 ; v3(24.74,38.67) 24.74,39.83 ; v3(24.74,38.67) 24.74,38.5
  BOTTOM w0.178: U2.1 32.96,24.24 U1.43
  vias: v3(11.71,8.88) v3(15.43,46.31) v3(17.68,38.47) v3(20.68,38.42) v3(26.67,18.23) v3(27.74,47.13) v3(28.63,38.7) v3(29.49,37.85) v3(31.29,47.13) v3(38.86,47.18)
SWD_CLK: length 16.5
  TOP w0.178: J1.4 15.8,30.95 v1(15.81,30.96)
  SHIELD w0.178: v1(27.57,30.05) 25.49,32.13 16.98,32.13 v1(15.81,30.96)
  BOTTOM w0.178: U1.27 26.99,28.7 26.99,29.46 27.21,29.67 27.21,29.68 v1(27.57,30.05)
SWD_DATA: length 19.7
  TOP w0.178: J1.5 15.42,33.49 v1(15.8,33.11)
  SHIELD w0.178: v1(15.8,33.11) 27.21,33.11 v1(28.7,31.62)
  BOTTOM w0.178: U1.26 26.63,28.5 26.63,29.85 28.19,31.41 28.19,31.41 28.41,31.62 v1(28.7,31.62)
TX: length 18.3
  SHIELD w0.178: v1(24.89,20.28) 22.64,18.03 14.31,18.03 v1(12.06,20.29)
  BOTTOM w0.178: U1.8 24.89,21.35 24.89,21.02 24.89,21.02 v1(24.89,20.28) ; TP1.1 12.06,19.77 12.06,19.77 v1(12.06,20.29)
VREF: length 26.3
  SHIELD w0.178: v1(39.78,24.79) 39.55,24.56 v1(39.55,18.23)
  BOTTOM w0.178: v1(39.78,24.79) C27.1 37.02,24.79 34.85,22.62 32.51,22.62 U1.45 ; U1.51 30.7,21.04 32.08,19.66 33.87,19.66 35.31,18.23 v1(39.55,18.23)
WAKEUP: length 23.9
  GND w0.178: v1(32.08,26.81) 32.08,27.34 32.04,27.37 32.04,29.77 32.97,30.7 32.97,39.94 v1(32.18,40.73)
  BOTTOM w0.178: U1.39 32.04,26.23 32.04,26.26 32.08,26.29 v1(32.08,26.81) ; SW2.3 SW2.1 33.13,41.67 v1(32.18,40.73)
XTAL24I: length 4.6
  BOTTOM w0.203: Y2.3 21.98,27.49 23.73,25.74 23.73,25.74 U1.16
XTAL24O: length 6.1
  BOTTOM w0.203: Y2.1 24.12,29.77 24.12,28.22 23.42,27.52 23.42,26.62 U1.17
XTAL32I: length 6.9
  BOTTOM w0.203: C1.1 26.77,14.89 26.52,15.14 Y1.1 26.52,20.14 U1.3
XTAL32O: length 7.6
  BOTTOM w0.203: U1.2 26.97,20.03 26.97,19.63 29.12,17.48 Y1.2 29.12,14.8 C2.1
N05559: length 2.2
  TOP w0.178: LED3.1 19.19,32.45 19.19,32.45 R6.2
N16776133: length 27.6
  SHIELD w0.178: v1(38.99,15.79) 38.99,36.16 v1(35.05,40.1)
  BOTTOM w0.178: R13.1 v1(38.99,15.79)
N16776137: length 20
  SHIELD w0.178: v1(36.7,27.75) 36.7,37.05 32.41,41.34 v1(32.41,42.78)
  BOTTOM w0.178: R12.1 34.66,27.29 35.12,27.75 v1(36.7,27.75)
N16776145: length 5.7
  SHIELD w0.178: v1(32.54,13.65) 37.06,13.65 v1(37.29,13.43)
  BOTTOM w0.178: v1(37.29,13.43) 37.29,14.26 R15.1
N16776149: length 41.6
  SHIELD w0.178: v1(5.84,16.22) 11.73,10.33 35.92,10.33 38.4,12.82 v1(38.4,17.31)
  BOTTOM w0.178: R11.1 38.38,17.34 v1(38.4,17.31)
N16783830: length 2.3
  BOTTOM w0.178: R2.2 LED2.1
N16783862: length 2.1
  BOTTOM w0.178: R1.2 LED1.1
N16783984: length 12.8
  TOP w1.016: TP3.1 18.83,21.29 17.31,21.29 C26.1 v4(12.4,21.7)
  BOTTOM w0.762: D3.2 8.2,23.28
  BOTTOM w1.016: v4(12.4,21.7) 10.82,23.28 8.2,23.28
N16844141: length 35.1
  GND w0.178: v1(25.01,44.49) 33.07,44.49 38.23,39.33 v1(38.23,20.46)
  BOTTOM w0.178: v1(38.23,20.46) R14.1
N16844145: length 66.3
  GND w0.178: v1(38.18,18.89) 39.07,19.78 39.07,40.02 33.27,45.81 6.71,45.81 4.24,43.35 v1(4.24,37.68)
  BOTTOM w0.178: v1(38.18,18.89) R16.1
N16865210: length 1.5
  BOTTOM w0.203: 23.44,22.16 U1.12
N16879821: length 4.5
  BOTTOM w0.178: 37.47,30.04 37.47,27.29 36.55,26.37 R10.1
N167810750: length 13.8
  TOP w0.508: v1(12.34,23.33) J1.1
  BOTTOM w0.508: v1(12.34,23.33) 10.31,25.36 3.81,25.36 3.3,24.86 D2.2

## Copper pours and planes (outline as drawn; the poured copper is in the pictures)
GND_SIGNAL on TOP: 13.51,35.19 27.51,35.19 27.51,21.19 13.51,21.19 ; 4 cut-outs
GND_SIGNAL on BOTTOM: 22.82,7.74 0.51,7.74 0.51,27.17 10.48,27.17 10.55,27.24 10.55,32.13 32.96,32.13 32.96,27.34 40.51,27.34 40.51,7.74 24.13,7.74 24.13,20.69 23.78,22.37 23.3,22.37 22.84,20.69 22.84,7.75 ; 8 cut-outs
GND_SIGNAL on BOTTOM: 10.63,1.06 10.63,0.57 16.86,0.57 16.86,4.38 17.49,4.38 17.49,0.57 19.14,0.57 19.14,4.38 19.78,4.38 19.78,0.57 21.43,0.57 21.43,4.38 22.06,4.38 22.06,0.57 23.72,0.57 23.72,7.69 23.69,8.26 23.69,18.4 23.28,18.4 23.28,8.26 23.25,7.69 23.25,7.67 23.25,6.9 16.31,6.9 16.31,6.4 23.25,6.4 23.25,1.06 22.61,1.06 22.61,4.87 20.96,4.87 20.96,1.06 20.33,1.06 20.33,4.87 18.67,4.87 18.67,1.06 18.04,1.06 18.04,4.87 16.39,4.87 16.39,1.06
GND_SIGNAL on BOTTOM: 12.31,34.27 12.32,34.7 12.32,35.06 12.82,35.56 12.84,35.66 12.76,35.71 11.31,35.71 10.33,34.73 10.33,34.51 10.27,34.59 10.17,34.58 9.92,34.32 9.92,31 9.42,31 9.45,31.03 9.45,39.18 0.55,39.18 0.55,39.16 0.51,39.16 0.51,48.19 14.33,48.19 14.33,47.61 14.48,47.46 14.48,40.08 26.51,40.08 26.51,47.31 26.57,47.31 26.59,47.33 26.59,48.19 40.51,48.19 40.51,40.22 40.48,40.22 40.48,40.22 32.98,40.22 32.98,33.64 32.97,33.64 32.97,31 10.34,31 10.34,32.46 10.79,32.46 10.79,32.72 10.34,32.72 10.34,34.27 ; 1 cut-out
GND_SIGNAL on GND: 0.51,31.41 40.51,31.41 40.51,7.74 40.51,7.74 22.85,7.74 22.85,6.09 0.51,6.09 0.51,6.09
GND_SIGNAL on GND: 0.51,30.8 0.51,48.19 40.51,48.19 40.51,30.8
VDD on BOTTOM: 23.62,23.46 23.75,23.46 24.26,23.97 24.26,24.09 24,24.35 24,24.47 24.26,24.73 24.26,24.86 23.81,25.3 21.62,25.3 21.46,25.15 21.46,24.4 21.6,24.27 22.81,24.27
SHIELD on TOP: 9.01,16.69 9.01,39.69 32.01,39.69 32.01,16.69 ; 1 cut-out
SHIELD on TOP: 0.51,8.19 0.51,48.19 40.51,48.19 40.51,8.19 ; 1 cut-out
SHIELD on SHIELD: 0.51,7.74 0.51,48.19 40.51,48.19 40.51,7.74 ; 4 cut-outs
N16776133 on TOP: 34.01,16.19 34.15,15.83 34.51,15.69 35.51,15.69 35.86,15.83 36.01,16.19 36.01,40.19 35.86,40.54 35.51,40.69 34.51,40.69 34.15,40.54 34.01,40.19
N16776137 on TOP: 8.01,43.19 8.15,43.54 8.51,43.69 32.51,43.69 32.86,43.54 33.01,43.19 33.01,42.19 32.86,41.83 32.51,41.69 8.51,41.69 8.15,41.83 8.01,42.19
N16776145 on TOP: 8.01,14.19 8.15,14.54 8.51,14.69 32.51,14.69 32.86,14.54 33.01,14.19 33.01,13.19 32.86,12.83 32.51,12.69 8.51,12.69 8.15,12.83 8.01,13.19
N16776149 on TOP: 5.51,15.69 5.15,15.83 5.01,16.19 5.01,40.19 5.15,40.54 5.51,40.69 6.51,40.69 6.86,40.54 7.01,40.19 7.01,16.19 6.86,15.83 6.51,15.69
N16844141 on BOTTOM: 15.51,41.69 15.65,41.33 16.01,41.19 25.01,41.19 25.36,41.33 25.51,41.69 25.51,45.69 25.36,46.04 25.01,46.19 16.01,46.19 15.65,46.04 15.51,45.69
N16844145 on BOTTOM: 6.5,28.19 6.85,28.33 7,28.69 7,37.69 6.85,38.04 6.5,38.19 2.5,38.19 2.15,38.04 2,37.69 2,28.69 2.15,28.33 2.5,28.19
N16865210 on BOTTOM: 23.69,18.9 23.69,20.56 23.62,22.24 23.34,22.24 23.28,20.56 23.28,18.9
N16879821 on BOTTOM: 38.52,29.2 38.87,29.35 39.02,29.7 39.02,38.7 38.87,39.06 38.52,39.2 34.52,39.2 34.16,39.06 34.02,38.7 34.02,29.7 34.16,29.35 34.52,29.2

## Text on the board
Ref Des/Assembly Bottom: ASSY SECONDARY SIDE
Board Geometry/Soldermask Bottom: SECONDARY SOLDERMASK
Package Geometry/Pastemask Bottom: SECONDARY SOLDER PASTE
Ref Des/Silkscreen Bottom: A | TX | RX | C | SECONDARY SILK SCREEN
User.Comments: RASB | C | 21/07/14 | 12230 World Trade Dr #200 | San Diego, CA 92128 | (858) 613-7900 | ALPHA RELEASE | RELEASE | CYPRESS | SEMICONDUCTOR | 01 | 02
Ref Des/Assembly Top: ASSY PRIMARY SIDE
Board Geometry/Soldermask Top: PRIMARY SOLDERMASK
Package Geometry/Pastemask Top: PRIMARY SOLDER PASTE
Ref Des/Silkscreen Top: PSOC 4 BLE-OPTICAL HRM | VDD | GND | PRIMARY SILK SCREEN
DIMENSION: 1 OF 1 | (PREFERRED) OR SILKSCREEN. | 1. RoHS COMPLIANT CERTIFICATION OR MATERIAL DECLARATION REQUIRED | 2. MATERIAL: | A. IS410 OR EQUIVALENT. MATERIAL MUST CONFORM TO UL94V-0. | B. USE HTE COPPER, AS SPECIFIED IN THE CROSS SECTION DIAGRAM | 3. DRILLING: | A. DIAMETERS IN DRILL TABLE ARE FINISHED HOLE SIZES +/-.003 tol. | UNLESS OTHERWISE SPECIFIED IN DRILL TABLE. | B. TEARDROP ALLOWED ON ENTRY OF VIA ON EVERY TRACE LAYER. | 4. PLATING: | COPPER PLATING IN THRU-HOLES .001 min. | 5. MARKING: | A. SILKSCREEN IN WHITE NON-CONDUCTIVE EPOXY INK ON PRIMARY SIDE OF THE | BOARD OR BOTH SIDES IF APPLICABLE. | B. FABRICATOR TO PLACE DATE CODE AND LOGO ON SECONDARY SIDE IN ETCH | 6. FINAL FABRICATION: | A. SOLDRMASK PRIMARY AND SECONDARY SIDE OF BOARD USING LIQUID PHOTOIMAGABLE | MASK MATERIAL OVER BARE COPPER. PER IPC-SM-840. MASK ARTWORKS PROVIDED | ARE 1:1. SOLDERMASK COLOR **BLUE** | 7. FINISH: | A. SHALL BE ELECTROLYTIC NICKEL/GOLD. ELECTROLESS NIKEL / IMMERSION GOLD. (ENIG) | B. NICKEL THICKNESS: 100-200 MICROINCHES. | C. GOLD THICKNESS: 3-10 MICROINCHES. | 8. BOARDS SHALL BE PURCHASED FROM UL RECOGNIZED VENDORS ONLY AND SHALL BE | MARKED IN COPPER ON SECONDARY SIDE OF BOARD WITH VENDORS UL IDENT. | FLAMABILITY RATING (94-V0), DATE CODE (WWYY), AND RoHS COMPILANT SYMBOL. | 9. MANUFACTURE BOARD TO BE IN ACCORDANCE WITH PERFORMANCE STANDARD | IPC-6011/6012 CLASS 2 BOARD TO BE INSPECTED PER IPC-600-A CLASS 2. | 10.MAXIMUM WRAP OR TWIST SHALL NOT EXCEED .007 in/in. | 11.TESTING: | A. FABRICATOR TO ADD TEST STRUCTURES OR CUPONS AS NEEDED. | B. T-LINE IMPEDENCE TO BE TESTED OR GUARANTEE WITHIN 10% IF SPECIFIED IN | C. OVERALL METAL TO METAL THICKNESS AS SPECIFIED IN THE CROSS SECTION | THE CROSS SECTION.  TOLERANCE TO BE +/-10% UNLESS OTHERWISE SPECIFIED. | * ALL DIMENSION IN MM | .062 +/- 10% | LAYER 1 SIGNAL 1/2 oz | LAYER 2 GROUND PLANE 1 oz | LAYER 3 POWER PLANE 1 oz | LAYER 4 SIGNAL 1/2 oz | FABRICATION DRAWING | PSOC 4 BLE-OPTICAL HRM | 610-60205-01 | PREPREG 0.0045 | CORE .018 1/0 | PREPREG 0.012 | NOTES:(UNLESS OTHERWISE SPECIFIED)
PAGE_OUTLINE: REV | CYPRESS PROPRIETARY | UNLESS OTHERWISE SPECIFIED | DIMENSIONS ARE IN INCHES | TOLERANCES ON; | 2 PL DECIMALS +/- .010 | 3 PL DECIMALS +/- .005 | THIRD ANGLE | PROJECTIONS | ANGLES +/- 2 | DRAWN | CHECKED | ENGRG | ISSUED | SIGNATURES | DATE | SCALE: | SIZE | 1/1 | FSCM NO | DWG NO | SHEET: | THIS DOCUMENT CONTAINS CONFIDENTAL, | PROPRIETARY INFORMATION THAT IS | CYPRESS SEMICONDUCTOR PROPERTY. | DO NOT DISCLOSE TO OR DUPLICATE FOR | OTHERS EXCEPT AS AUTHORIZED BY CYPRESS. | DESCRIPTION | REVISIONS | APPROVED | D | C | B | A | 4 | 3 | 2 | 1
COMPVAL_TYPE_BOTTOM: PSOC 4 BLE-OPTICAL HRM PRIMARY SIDE
COMPVAL_TYPE_TOP: L02_SHIELD
DEVICE_TYPE_TOP: L03_GND
USER_PART_NUM_TOP: SECONDARY SIDE
User.14: FIGURE | SIZE | 10.0 | 12.0 | 13.0 | 15.0 | 20.0 | DRILL CHART: TOP to BOTTOM | ALL UNITS ARE IN MILS | PLATED | QTY | 57 | 1 | 9
User.15: FIGURE | SIZE | 12.0 | DRILL CHART: GND to BOTTOM | ALL UNITS ARE IN MILS | PLATED | QTY | 215
User.16: FIGURE | SIZE | 12.0 | DRILL CHART: TOP to SHIELD | ALL UNITS ARE IN MILS | PLATED | QTY | 60
